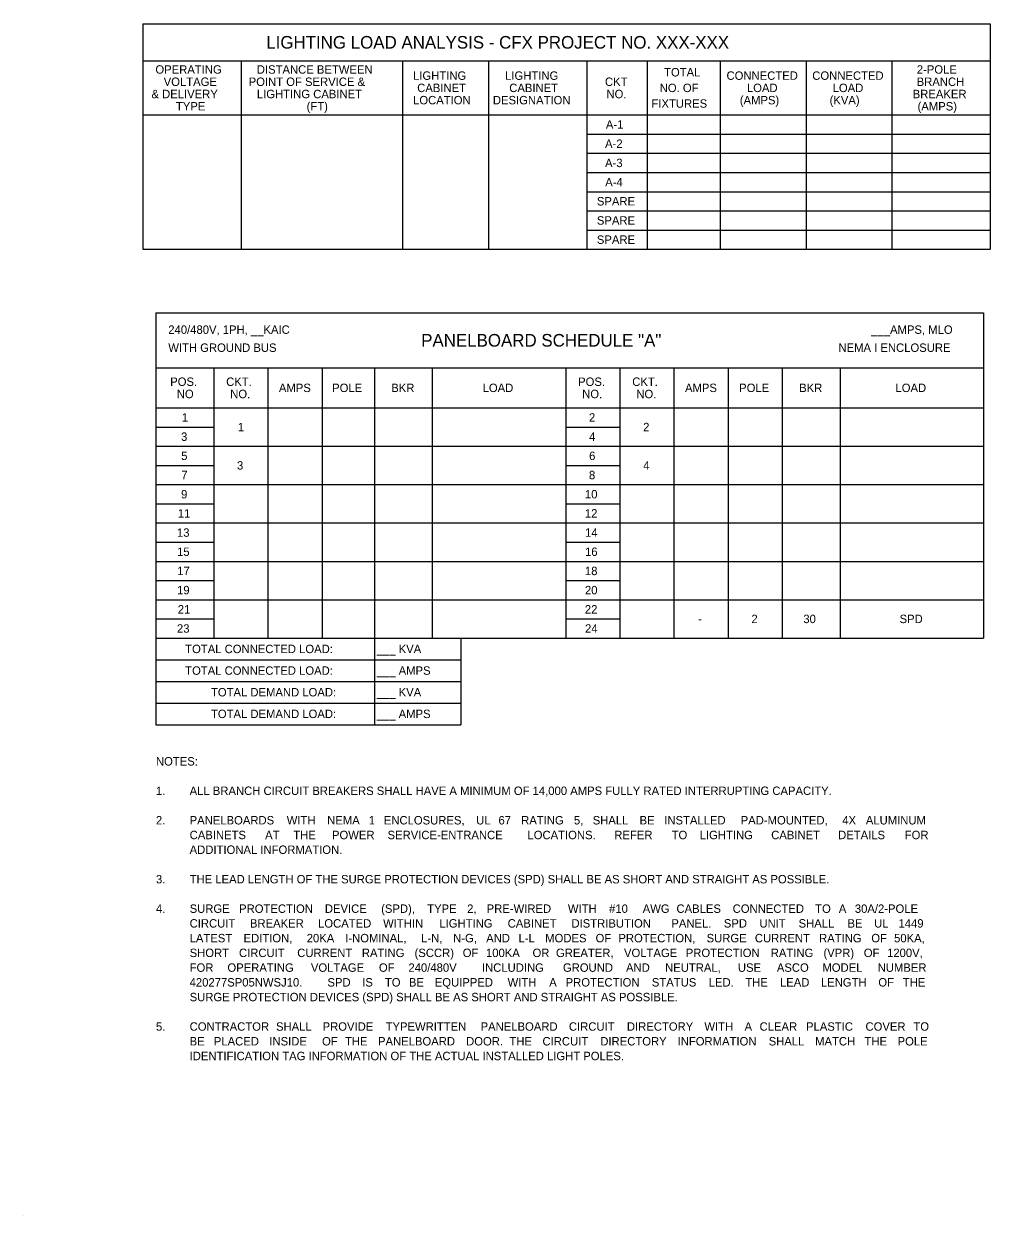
# Model space of a CAD drawing. Extents: x 856079 to 2148480, y 462635 to 2147771.
# Drawn here: x 2148464.67 to 2148472.7, y 2147761.57 to 2147771.47 of the extents above; entities that cross this region are included whole.
import ezdxf

# ---------------------------------------------------------------- set-up
doc = ezdxf.new("R2010")
doc.units = 0
for name, color, linetype in [('AdhocPoint_dp', 7, 'Continuous'), ('FLMap5', 7, 'Continuous'), ('SumBoxBorder_dp', 7, 'Continuous'), ('SumBoxLines_dp', 7, 'Continuous'), ('TextNotes', 7, 'Continuous')]:
    doc.layers.add(name, color=color, linetype=linetype)

msp = doc.modelspace()

# ---------------------------------------------------------------- linework, layer by layer
at = {"layer": 'AdhocPoint_dp'}
msp.add_line((2148464.6682, 2147761.5674), (2148464.6682, 2147761.5674), dxfattribs=at)
at = {"layer": 'SumBoxBorder_dp'}
for p, q in [((2148465.6565, 2147771.4724), (2148472.699, 2147771.4724)), ((2148465.6565, 2147771.4724), (2148465.6565, 2147769.5984)), ((2148472.699, 2147771.4724), (2148472.699, 2147769.5984)), ((2148465.6565, 2147771.1649), (2148472.699, 2147771.1649)), ((2148465.6565, 2147771.1649), (2148472.699, 2147771.1649)), ((2148465.6565, 2147769.5984), (2148472.699, 2147769.5984)), ((2148465.7662, 2147769.0699), (2148472.6437, 2147769.0699)), ((2148465.7662, 2147769.0699), (2148465.7662, 2147765.6454)), ((2148472.6437, 2147769.0699), (2148472.6437, 2147766.3654)), ((2148465.7662, 2147768.6124), (2148472.6437, 2147768.6124)), ((2148465.7662, 2147768.6124), (2148472.6437, 2147768.6124)), ((2148465.7662, 2147766.3654), (2148472.6437, 2147766.3654)), ((2148465.7662, 2147766.3654), (2148472.6437, 2147766.3654)), ((2148467.5812, 2147766.3654), (2148467.5812, 2147765.6454)), ((2148468.3012, 2147766.3654), (2148468.3012, 2147765.6454)), ((2148468.3012, 2147766.3654), (2148468.3012, 2147765.6454)), ((2148465.7662, 2147766.1854), (2148468.3012, 2147766.1854)), ((2148465.7662, 2147766.1854), (2148468.3012, 2147766.1854)), ((2148465.7662, 2147766.0054), (2148468.3012, 2147766.0054)), ((2148465.7662, 2147766.0054), (2148468.3012, 2147766.0054)), ((2148465.7662, 2147765.8254), (2148468.3012, 2147765.8254)), ((2148465.7662, 2147765.8254), (2148468.3012, 2147765.8254)), ((2148465.7662, 2147765.6454), (2148468.3012, 2147765.6454))]:
    msp.add_line(p, q, dxfattribs=at)
at = {"layer": 'SumBoxLines_dp'}
for p, q in [((2148466.474, 2147771.1649), (2148466.474, 2147769.5984)), ((2148466.474, 2147771.1649), (2148466.474, 2147769.5984)), ((2148467.8165, 2147771.1649), (2148467.8165, 2147769.5984)), ((2148467.8165, 2147771.1649), (2148467.8165, 2147769.5984)), ((2148468.529, 2147771.1649), (2148468.529, 2147769.5984)), ((2148468.529, 2147771.1649), (2148468.529, 2147769.5984)), ((2148469.3465, 2147771.1649), (2148469.3465, 2147769.5984)), ((2148469.3465, 2147771.1649), (2148469.3465, 2147769.5984)), ((2148469.849, 2147771.1649), (2148469.849, 2147769.5984)), ((2148469.849, 2147771.1649), (2148469.849, 2147769.5984)), ((2148470.4565, 2147771.1649), (2148470.4565, 2147769.5984)), ((2148470.4565, 2147771.1649), (2148470.4565, 2147769.5984)), ((2148471.169, 2147771.1649), (2148471.169, 2147769.5984)), ((2148471.169, 2147771.1649), (2148471.169, 2147769.5984)), ((2148471.8815, 2147771.1649), (2148471.8815, 2147769.5984)), ((2148471.8815, 2147771.1649), (2148471.8815, 2147769.5984)), ((2148465.6565, 2147770.7149), (2148472.699, 2147770.7149)), ((2148465.6565, 2147770.7149), (2148472.699, 2147770.7149)), ((2148469.3465, 2147770.5554), (2148472.699, 2147770.5554)), ((2148469.3465, 2147770.5554), (2148472.699, 2147770.5554)), ((2148469.3465, 2147770.3959), (2148472.699, 2147770.3959)), ((2148469.3465, 2147770.3959), (2148472.699, 2147770.3959)), ((2148469.3465, 2147770.2364), (2148472.699, 2147770.2364)), ((2148469.3465, 2147770.2364), (2148472.699, 2147770.2364)), ((2148469.3465, 2147770.0769), (2148472.699, 2147770.0769)), ((2148469.3465, 2147770.0769), (2148472.699, 2147770.0769)), ((2148469.3465, 2147769.9174), (2148472.699, 2147769.9174)), ((2148469.3465, 2147769.9174), (2148472.699, 2147769.9174)), ((2148469.3465, 2147769.7579), (2148472.699, 2147769.7579)), ((2148469.3465, 2147769.7579), (2148472.699, 2147769.7579)), ((2148466.2462, 2147768.6124), (2148466.2462, 2147766.3654)), ((2148466.2462, 2147768.6124), (2148466.2462, 2147766.3654)), ((2148466.6962, 2147768.6124), (2148466.6962, 2147766.3654)), ((2148466.6962, 2147768.6124), (2148466.6962, 2147766.3654)), ((2148467.1462, 2147768.6124), (2148467.1462, 2147766.3654)), ((2148467.1462, 2147768.6124), (2148467.1462, 2147766.3654)), ((2148467.5812, 2147768.6124), (2148467.5812, 2147766.3654)), ((2148467.5812, 2147768.6124), (2148467.5812, 2147766.3654)), ((2148468.0612, 2147768.6124), (2148468.0612, 2147766.3654)), ((2148468.0612, 2147768.6124), (2148468.0612, 2147766.3654)), ((2148469.1712, 2147768.6124), (2148469.1712, 2147766.3654)), ((2148469.1712, 2147768.6124), (2148469.1712, 2147766.3654)), ((2148469.6212, 2147768.6124), (2148469.6212, 2147766.3654)), ((2148469.6212, 2147768.6124), (2148469.6212, 2147766.3654)), ((2148470.0712, 2147768.6124), (2148470.0712, 2147766.3654)), ((2148470.0712, 2147768.6124), (2148470.0712, 2147766.3654)), ((2148470.5212, 2147768.6124), (2148470.5212, 2147766.3654)), ((2148470.5212, 2147768.6124), (2148470.5212, 2147766.3654)), ((2148470.9712, 2147768.6124), (2148470.9712, 2147766.3654)), ((2148470.9712, 2147768.6124), (2148470.9712, 2147766.3654)), ((2148471.4512, 2147768.6124), (2148471.4512, 2147766.3654)), ((2148471.4512, 2147768.6124), (2148471.4512, 2147766.3654)), ((2148465.7662, 2147768.2794), (2148472.6437, 2147768.2794)), ((2148465.7662, 2147768.2794), (2148472.6437, 2147768.2794)), ((2148465.7662, 2147768.1199), (2148466.2462, 2147768.1199)), ((2148465.7662, 2147768.1199), (2148466.2462, 2147768.1199)), ((2148469.1712, 2147768.1199), (2148469.6212, 2147768.1199)), ((2148465.7662, 2147767.9604), (2148472.6437, 2147767.9604)), ((2148465.7662, 2147767.9604), (2148472.6437, 2147767.9604)), ((2148465.7662, 2147767.8009), (2148466.2462, 2147767.8009)), ((2148465.7662, 2147767.8009), (2148466.2462, 2147767.8009)), ((2148469.1712, 2147767.8009), (2148469.6212, 2147767.8009)), ((2148469.1712, 2147767.8009), (2148469.6212, 2147767.8009)), ((2148465.7662, 2147767.6414), (2148469.1712, 2147767.6414)), ((2148465.7662, 2147767.6414), (2148472.6437, 2147767.6414)), ((2148469.6212, 2147767.6414), (2148472.6437, 2147767.6414)), ((2148465.7662, 2147767.4819), (2148466.2462, 2147767.4819)), ((2148465.7662, 2147767.4819), (2148466.2462, 2147767.4819)), ((2148469.1712, 2147767.4819), (2148469.6212, 2147767.4819)), ((2148469.1712, 2147767.4819), (2148469.6212, 2147767.4819)), ((2148465.7662, 2147767.3224), (2148472.6437, 2147767.3224)), ((2148465.7662, 2147767.3224), (2148472.6437, 2147767.3224)), ((2148465.7662, 2147767.1629), (2148466.2462, 2147767.1629)), ((2148465.7662, 2147767.1629), (2148466.2462, 2147767.1629)), ((2148469.1712, 2147767.1629), (2148469.6212, 2147767.1629)), ((2148465.7662, 2147767.0034), (2148472.6437, 2147767.0034)), ((2148465.7662, 2147767.0034), (2148472.6437, 2147767.0034)), ((2148465.7662, 2147766.8439), (2148466.2462, 2147766.8439)), ((2148465.7662, 2147766.8439), (2148466.2462, 2147766.8439)), ((2148469.1712, 2147766.8439), (2148469.6212, 2147766.8439)), ((2148469.1712, 2147766.8439), (2148469.6212, 2147766.8439)), ((2148465.7662, 2147766.6844), (2148469.1712, 2147766.6844)), ((2148465.7662, 2147766.6844), (2148472.6437, 2147766.6844)), ((2148469.6212, 2147766.6844), (2148472.6437, 2147766.6844)), ((2148465.7662, 2147766.5249), (2148466.2462, 2147766.5249)), ((2148465.7662, 2147766.5249), (2148466.2462, 2147766.5249)), ((2148469.1712, 2147766.5249), (2148469.6212, 2147766.5249)), ((2148469.1712, 2147766.5249), (2148469.6212, 2147766.5249))]:
    msp.add_line(p, q, dxfattribs=at)

# ---------------------------------------------------------------- texts
at = {"layer": 'FLMap5'}
for s, height, p in [('LIGHTING LOAD ANALYSIS - CFX PROJECT NO. XXX-XXX', 0.105, (2148466.6829, 2147771.2662)), ('OPERATING', 0.07, (2148465.7617, 2147771.0579)), ('DISTANCE BETWEEN', 0.07, (2148466.6045, 2147771.0579)), ('TOTAL', 0.07, (2148469.9891, 2147771.0349)), ('2-POLE', 0.07, (2148472.0893, 2147771.0579)), ('VOLTAGE', 0.07, (2148465.8304, 2147770.9559)), ('POINT OF SERVICE &', 0.07, (2148466.5368, 2147770.9559)), ('LIGHTING', 0.07, (2148467.9031, 2147771.0069)), ('LIGHTING', 0.07, (2148468.6681, 2147771.0069)), ('CKT', 0.07, (2148469.4979, 2147770.9559)), ('CONNECTED', 0.07, (2148470.5081, 2147771.0069)), ('CONNECTED', 0.07, (2148471.2206, 2147771.0069)), ('BRANCH', 0.07, (2148472.0883, 2147770.9559)), ('& DELIVERY', 0.07, (2148465.7289, 2147770.8539)), ('LIGHTING CABINET', 0.07, (2148466.605, 2147770.8539)), ('CABINET', 0.07, (2148467.9374, 2147770.9049)), ('CABINET', 0.07, (2148468.7024, 2147770.9049)), ('NO.', 0.07, (2148469.5101, 2147770.8539)), ('NO. OF', 0.07, (2148469.9528, 2147770.9049)), ('LOAD', 0.07, (2148470.6775, 2147770.9049)), ('LOAD', 0.07, (2148471.39, 2147770.9049)), ('BREAKER', 0.07, (2148472.0553, 2147770.8539)), ('TYPE', 0.07, (2148465.932, 2147770.7519)), ('(FT)', 0.07, (2148467.0184, 2147770.7519)), ('LOCATION', 0.07, (2148467.9031, 2147770.8029)), ('DESIGNATION', 0.07, (2148468.5664, 2147770.8029)), ('FIXTURES', 0.07, (2148469.8842, 2147770.7749)), ('(AMPS)', 0.07, (2148470.6182, 2147770.8029)), ('(KVA)', 0.07, (2148471.3646, 2147770.8029)), ('(AMPS)', 0.07, (2148472.0957, 2147770.7519)), ('A-1', 0.07, (2148469.5054, 2147770.6002)), ('A-2', 0.07, (2148469.4986, 2147770.4407)), ('A-3', 0.07, (2148469.4986, 2147770.2812)), ('A-4', 0.07, (2148469.5, 2147770.1217)), ('SPARE', 0.07, (2148469.4306, 2147769.9622)), ('SPARE', 0.07, (2148469.4306, 2147769.8027)), ('SPARE', 0.07, (2148469.4306, 2147769.6432)), ('240/480V, 1PH, __KAIC', 0.07, (2148465.8687, 2147768.8949)), ('___AMPS, MLO', 0.07, (2148471.7109, 2147768.8949)), ('WITH GROUND BUS', 0.07, (2148465.8687, 2147768.7449)), ('PANELBOARD SCHEDULE "A"', 0.105, (2148467.9705, 2147768.7887)), ('NEMA I ENCLOSURE', 0.07, (2148471.4385, 2147768.7449)), ('POS.', 0.07, (2148465.8847, 2147768.4619)), ('CKT.', 0.07, (2148466.3497, 2147768.4619)), ('POS.', 0.07, (2148469.2747, 2147768.4619)), ('CKT.', 0.07, (2148469.7247, 2147768.4619)), ('NO', 0.07, (2148465.9394, 2147768.3599)), ('NO.', 0.07, (2148466.3835, 2147768.3599)), ('AMPS', 0.07, (2148466.7881, 2147768.4109)), ('POLE', 0.07, (2148467.2304, 2147768.4109)), ('BKR', 0.07, (2148467.7217, 2147768.4109)), ('LOAD', 0.07, (2148468.481, 2147768.4109)), ('NO.', 0.07, (2148469.3085, 2147768.3599)), ('NO.', 0.07, (2148469.7585, 2147768.3599)), ('AMPS', 0.07, (2148470.1631, 2147768.4109)), ('POLE', 0.07, (2148470.6129, 2147768.4109)), ('BKR', 0.07, (2148471.1117, 2147768.4109)), ('LOAD', 0.07, (2148471.9122, 2147768.4109)), ('1', 0.07, (2148465.9815, 2147768.1647)), ('2', 0.07, (2148469.3648, 2147768.1647)), ('1', 0.07, (2148466.4465, 2147768.0849)), ('2', 0.07, (2148469.8148, 2147768.0849)), ('3', 0.07, (2148465.9748, 2147768.0052)), ('4', 0.07, (2148469.3662, 2147768.0052)), ('5', 0.07, (2148465.9757, 2147767.8457)), ('6', 0.07, (2148469.3662, 2147767.8457)), ('3', 0.07, (2148466.4398, 2147767.7659)), ('4', 0.07, (2148469.8162, 2147767.7659)), ('7', 0.07, (2148465.9768, 2147767.6862)), ('8', 0.07, (2148469.365, 2147767.6862)), ('9', 0.07, (2148465.9752, 2147767.5267)), ('10', 0.07, (2148469.3315, 2147767.5267)), ('11', 0.07, (2148465.9477, 2147767.3672)), ('12', 0.07, (2148469.3309, 2147767.3672)), ('13', 0.07, (2148465.9409, 2147767.2077)), ('14', 0.07, (2148469.3323, 2147767.2077)), ('16', 0.07, (2148469.3323, 2147767.0482)), ('15', 0.07, (2148465.9418, 2147767.0482)), ('17', 0.07, (2148465.9429, 2147766.8887)), ('18', 0.07, (2148469.3312, 2147766.8887)), ('19', 0.07, (2148465.9413, 2147766.7292)), ('20', 0.07, (2148469.3315, 2147766.7292)), ('21', 0.07, (2148465.9477, 2147766.5697)), ('22', 0.07, (2148469.3309, 2147766.5697)), ('2', 0.07, (2148470.7148, 2147766.4899)), ('30', 0.07, (2148471.1465, 2147766.4899)), ('SPD', 0.07, (2148471.9461, 2147766.4899)), ('23', 0.07, (2148465.9409, 2147766.4102)), ('24', 0.07, (2148469.3323, 2147766.4102)), ('-', 0.07, (2148470.2727, 2147766.4899)), ('TOTAL CONNECTED LOAD:', 0.07, (2148466.0093, 2147766.2404)), ('___ KVA', 0.07, (2148467.6012, 2147766.2404)), ('TOTAL CONNECTED LOAD:', 0.07, (2148466.0093, 2147766.0604)), ('___ AMPS', 0.07, (2148467.6012, 2147766.0604)), ('TOTAL DEMAND LOAD:', 0.07, (2148466.2233, 2147765.8804)), ('___ KVA', 0.07, (2148467.6012, 2147765.8804)), ('TOTAL DEMAND LOAD:', 0.07, (2148466.2233, 2147765.7004)), ('___ AMPS', 0.07, (2148467.6012, 2147765.7004))]:
    msp.add_text(s, height=height, dxfattribs=at).set_placement(p)
at = {"layer": 'TextNotes'}
for s, p in [('NOTES:', (2148465.7662, 2147765.3059)), ('1.', (2148465.7662, 2147765.0609)), ('ALL BRANCH CIRCUIT BREAKERS SHALL HAVE A MINIMUM OF 14,000 AMPS FULLY RATED INTERRUPTING CAPACITY.', (2148466.0462, 2147765.0609)), ('2.', (2148465.7662, 2147764.8159)), ('PANELBOARDS ', (2148466.0462, 2147764.8159)), ('WITH ', (2148466.8531, 2147764.8159)), ('NEMA ', (2148467.1892, 2147764.8159)), ('1 ', (2148467.5342, 2147764.8159)), ('ENCLOSURES, ', (2148467.6599, 2147764.8159)), ('UL ', (2148468.4276, 2147764.8159)), ('67 ', (2148468.613, 2147764.8159)), ('RATING ', (2148468.8015, 2147764.8159)), ('5, ', (2148469.2397, 2147764.8159)), ('SHALL ', (2148469.396, 2147764.8159)), ('BE ', (2148469.7854, 2147764.8159)), ('INSTALLED ', (2148469.9904, 2147764.8159)), ('PAD-MOUNTED, ', (2148470.6258, 2147764.8159)), ('4X ', (2148471.4699, 2147764.8159)), ('ALUMINUM ', (2148471.6658, 2147764.8159)), ('CABINETS ', (2148466.0462, 2147764.6934)), ('AT ', (2148466.6733, 2147764.6934)), ('THE ', (2148466.9072, 2147764.6934)), ('POWER ', (2148467.229, 2147764.6934)), ('SERVICE-ENTRANCE ', (2148467.691, 2147764.6934)), ('LOCATIONS. ', (2148468.8538, 2147764.6934)), (' REFER ', (2148469.5492, 2147764.6934)), ('TO ', (2148470.0517, 2147764.6934)), ('LIGHTING ', (2148470.2851, 2147764.6934)), ('CABINET ', (2148470.8792, 2147764.6934)), ('DETAILS ', (2148471.4355, 2147764.6934)), ('FOR ', (2148471.9891, 2147764.6934)), ('ADDITIONAL INFORMATION.', (2148466.0462, 2147764.5709)), ('3.', (2148465.7662, 2147764.3259)), ('THE LEAD LENGTH OF THE SURGE PROTECTION DEVICES (SPD) SHALL BE AS SHORT AND STRAIGHT AS POSSIBLE.', (2148466.0462, 2147764.3259)), ('4.', (2148465.7662, 2147764.0809)), ('SURGE ', (2148466.0462, 2147764.0809)), ('PROTECTION ', (2148466.4572, 2147764.0809)), ('DEVICE ', (2148467.17, 2147764.0809)), ('(SPD), ', (2148467.6377, 2147764.0809)), ('TYPE ', (2148468.0205, 2147764.0809)), ('2, ', (2148468.3525, 2147764.0809)), ('PRE-WIRED ', (2148468.5148, 2147764.0809)), ('WITH ', (2148469.1899, 2147764.0809)), ('#10 ', (2148469.5321, 2147764.0809)), ('AWG ', (2148469.8114, 2147764.0809)), ('CABLES ', (2148470.0921, 2147764.0809)), ('CONNECTED ', (2148470.5591, 2147764.0809)), ('TO ', (2148471.245, 2147764.0809)), ('A ', (2148471.4413, 2147764.0809)), ('30A/2-POLE ', (2148471.5744, 2147764.0809)), ('CIRCUIT ', (2148466.0462, 2147763.9584)), ('BREAKER ', (2148466.5472, 2147763.9584)), ('LOCATED ', (2148467.1135, 2147763.9584)), ('WITHIN ', (2148467.654, 2147763.9584)), ('LIGHTING ', (2148468.1216, 2147763.9584)), ('CABINET ', (2148468.6893, 2147763.9584)), ('DISTRIBUTION ', (2148469.2193, 2147763.9584)), ('PANEL. ', (2148470.0496, 2147763.9584)), ('SPD ', (2148470.4858, 2147763.9584)), ('UNIT ', (2148470.7817, 2147763.9584)), ('SHALL ', (2148471.1069, 2147763.9584)), ('BE ', (2148471.5131, 2147763.9584)), ('UL ', (2148471.7348, 2147763.9584)), ('1449 ', (2148471.937, 2147763.9584)), ('LATEST ', (2148466.0462, 2147763.8359)), ('EDITION, ', (2148466.4942, 2147763.8359)), ('20KA ', (2148467.0192, 2147763.8359)), ('I-NOMINAL, ', (2148467.3393, 2147763.8359)), ('L-N, ', (2148467.9703, 2147763.8359)), ('N-G, ', (2148468.2361, 2147763.8359)), ('AND ', (2148468.5106, 2147763.8359)), ('L-L ', (2148468.7797, 2147763.8359)), ('MODES ', (2148469.0011, 2147763.8359)), ('OF ', (2148469.4198, 2147763.8359)), ('PROTECTION, ', (2148469.6094, 2147763.8359)), ('SURGE ', (2148470.3427, 2147763.8359)), ('CURRENT ', (2148470.7435, 2147763.8359)), ('RATING ', (2148471.2769, 2147763.8359)), ('OF ', (2148471.7111, 2147763.8359)), ('50KA, ', (2148471.9007, 2147763.8359)), ('SHORT ', (2148466.0462, 2147763.7134)), ('CIRCUIT ', (2148466.4564, 2147763.7134)), ('CURRENT ', (2148466.9403, 2147763.7134)), ('RATING ', (2148467.4775, 2147763.7134)), ('(SCCR) ', (2148467.9154, 2147763.7134)), ('OF ', (2148468.3157, 2147763.7134)), ('100KA ', (2148468.5091, 2147763.7134)), ('OR ', (2148468.8958, 2147763.7134)), ('GREATER, ', (2148469.0907, 2147763.7134)), ('VOLTAGE ', (2148469.656, 2147763.7134)), ('PROTECTION ', (2148470.1694, 2147763.7134)), ('RATING ', (2148470.8758, 2147763.7134)), ('(VPR) ', (2148471.3137, 2147763.7134)), ('OF ', (2148471.649, 2147763.7134)), ('1200V, ', (2148471.8424, 2147763.7134)), ('FOR ', (2148466.0462, 2147763.5909)), ('OPERATING ', (2148466.3603, 2147763.5909)), ('VOLTAGE ', (2148467.0539, 2147763.5909)), ('OF ', (2148467.6192, 2147763.5909)), ('240/480V ', (2148467.8646, 2147763.5909)), ('INCLUDING ', (2148468.4754, 2147763.5909)), ('GROUND ', (2148469.1484, 2147763.5909)), ('AND ', (2148469.6727, 2147763.5909)), ('NEUTRAL, ', (2148469.9976, 2147763.5909)), ('USE ', (2148470.6026, 2147763.5909)), ('ASCO ', (2148470.9263, 2147763.5909)), ('MODEL ', (2148471.305, 2147763.5909)), ('NUMBER ', (2148471.7642, 2147763.5909)), ('420277SP05NWSJ10. ', (2148466.0462, 2147763.4684)), ('SPD ', (2148467.1915, 2147763.4684)), ('IS ', (2148467.4803, 2147763.4684)), ('TO ', (2148467.6688, 2147763.4684)), ('BE ', (2148467.8687, 2147763.4684)), ('EQUIPPED ', (2148468.0833, 2147763.4684)), ('WITH ', (2148468.6887, 2147763.4684)), ('A ', (2148469.0345, 2147763.4684)), ('PROTECTION ', (2148469.1711, 2147763.4684)), ('STATUS ', (2148469.8875, 2147763.4684)), ('LED. ', (2148470.3602, 2147763.4684)), ('THE ', (2148470.6639, 2147763.4684)), ('LEAD ', (2148470.9522, 2147763.4684)), ('LENGTH ', (2148471.2925, 2147763.4684)), ('OF ', (2148471.7697, 2147763.4684)), ('THE ', (2148471.973, 2147763.4684)), ('SURGE PROTECTION DEVICES (SPD) SHALL BE AS SHORT AND STRAIGHT AS POSSIBLE.', (2148466.0462, 2147763.3459)), ('5.', (2148465.7662, 2147763.1009)), ('CONTRACTOR ', (2148466.0462, 2147763.1009)), ('SHALL ', (2148466.764, 2147763.1009)), ('PROVIDE ', (2148467.1512, 2147763.1009)), ('TYPEWRITTEN ', (2148467.6747, 2147763.1009)), ('PANELBOARD ', (2148468.4642, 2147763.1009)), ('CIRCUIT ', (2148469.1981, 2147763.1009)), ('DIRECTORY ', (2148469.6801, 2147763.1009)), ('WITH ', (2148470.3241, 2147763.1009)), ('A ', (2148470.658, 2147763.1009)), ('CLEAR ', (2148470.7827, 2147763.1009)), ('PLASTIC ', (2148471.1687, 2147763.1009)), ('COVER ', (2148471.663, 2147763.1009)), ('TO ', (2148472.0613, 2147763.1009)), ('BE ', (2148466.0462, 2147762.9784)), ('PLACED ', (2148466.2474, 2147762.9784)), ('INSIDE ', (2148466.7086, 2147762.9784)), ('OF ', (2148467.1467, 2147762.9784)), ('THE ', (2148467.3367, 2147762.9784)), ('PANELBOARD ', (2148467.6116, 2147762.9784)), ('DOOR. ', (2148468.344, 2147762.9784)), ('THE ', (2148468.7037, 2147762.9784)), ('CIRCUIT ', (2148468.9785, 2147762.9784)), ('DIRECTORY ', (2148469.4591, 2147762.9784)), ('INFORMATION ', (2148470.1016, 2147762.9784)), ('SHALL ', (2148470.8585, 2147762.9784)), ('MATCH ', (2148471.2442, 2147762.9784)), ('THE ', (2148471.6548, 2147762.9784)), ('POLE ', (2148471.9297, 2147762.9784)), ('IDENTIFICATION TAG INFORMATION OF THE ACTUAL INSTALLED LIGHT POLES.', (2148466.0462, 2147762.8559))]:
    msp.add_text(s, height=0.07, dxfattribs=at).set_placement(p)

doc.saveas('drawing.dxf')
